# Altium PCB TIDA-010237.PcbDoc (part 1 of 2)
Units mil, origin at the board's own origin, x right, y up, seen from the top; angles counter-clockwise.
Board outline 2362.2 x 3346.46 mil, 4 copper layers (Top Layer, GND, Power, Bottom Layer), stack 61.6 mil thick; 143 components, 71 nets, 356 pads, 186 vias.
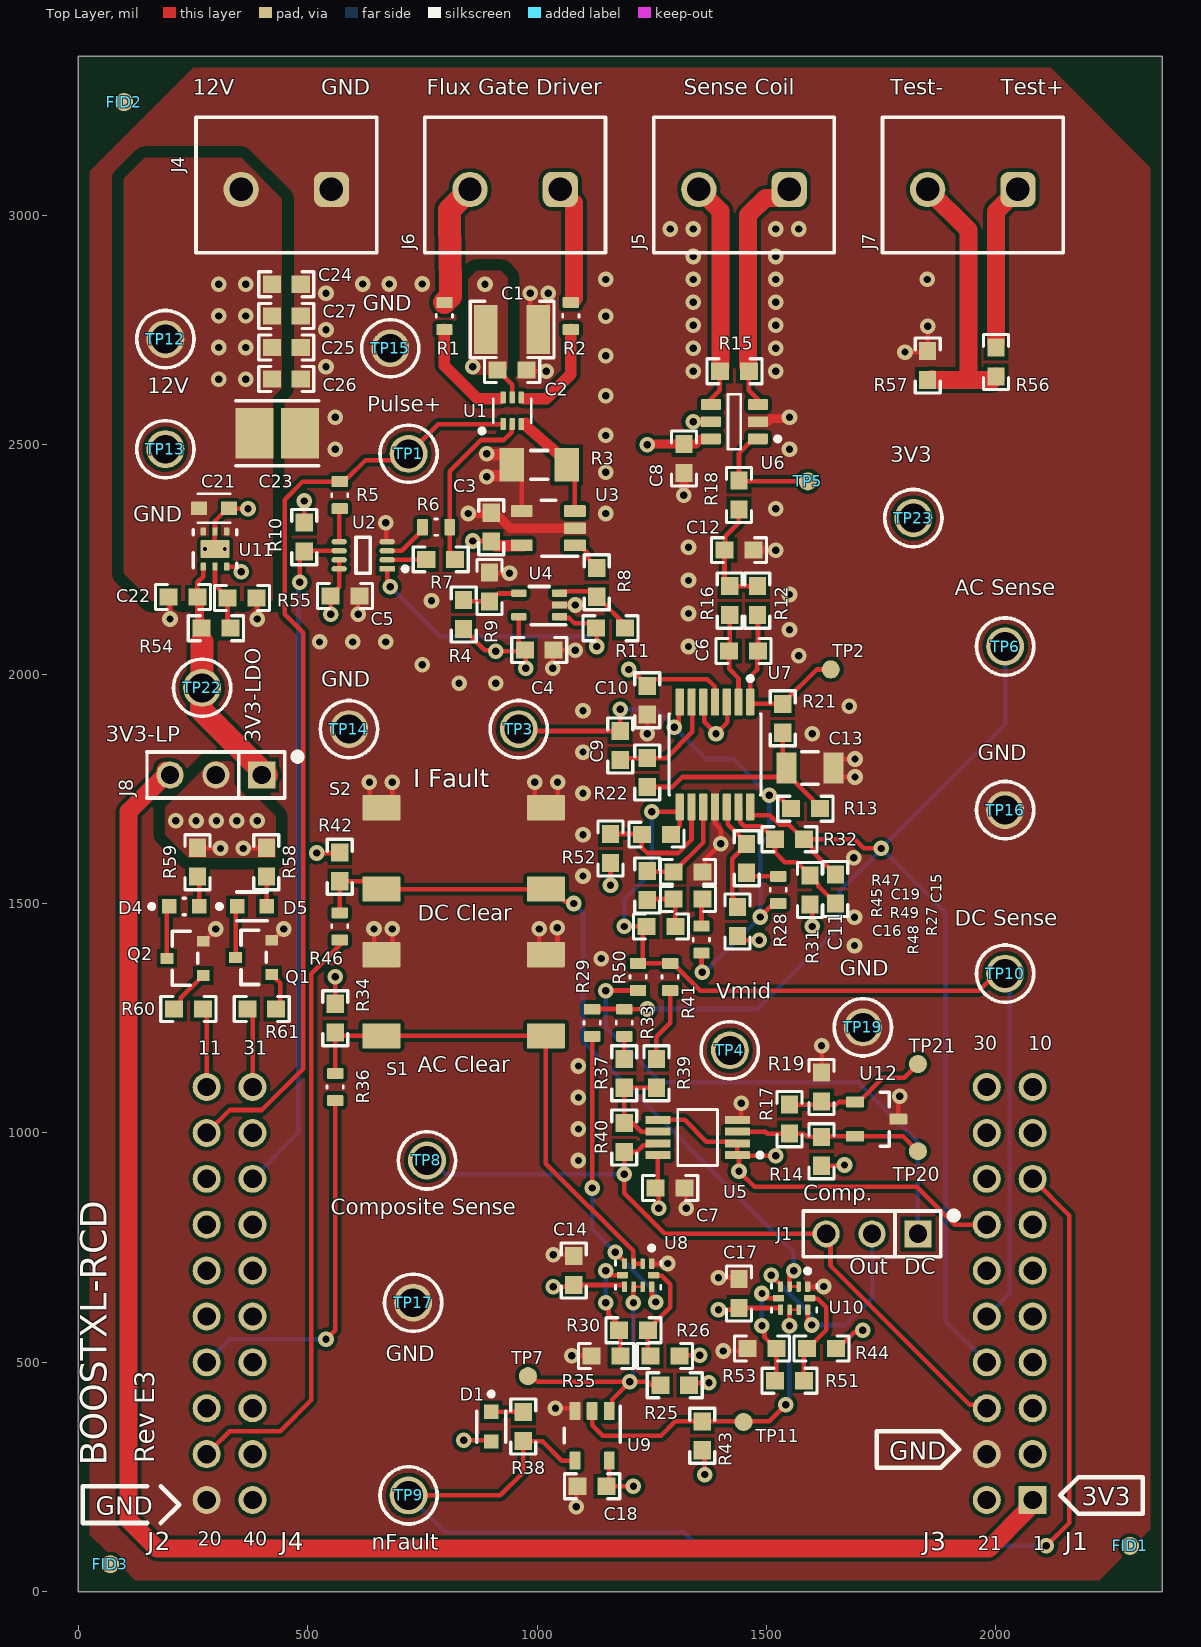
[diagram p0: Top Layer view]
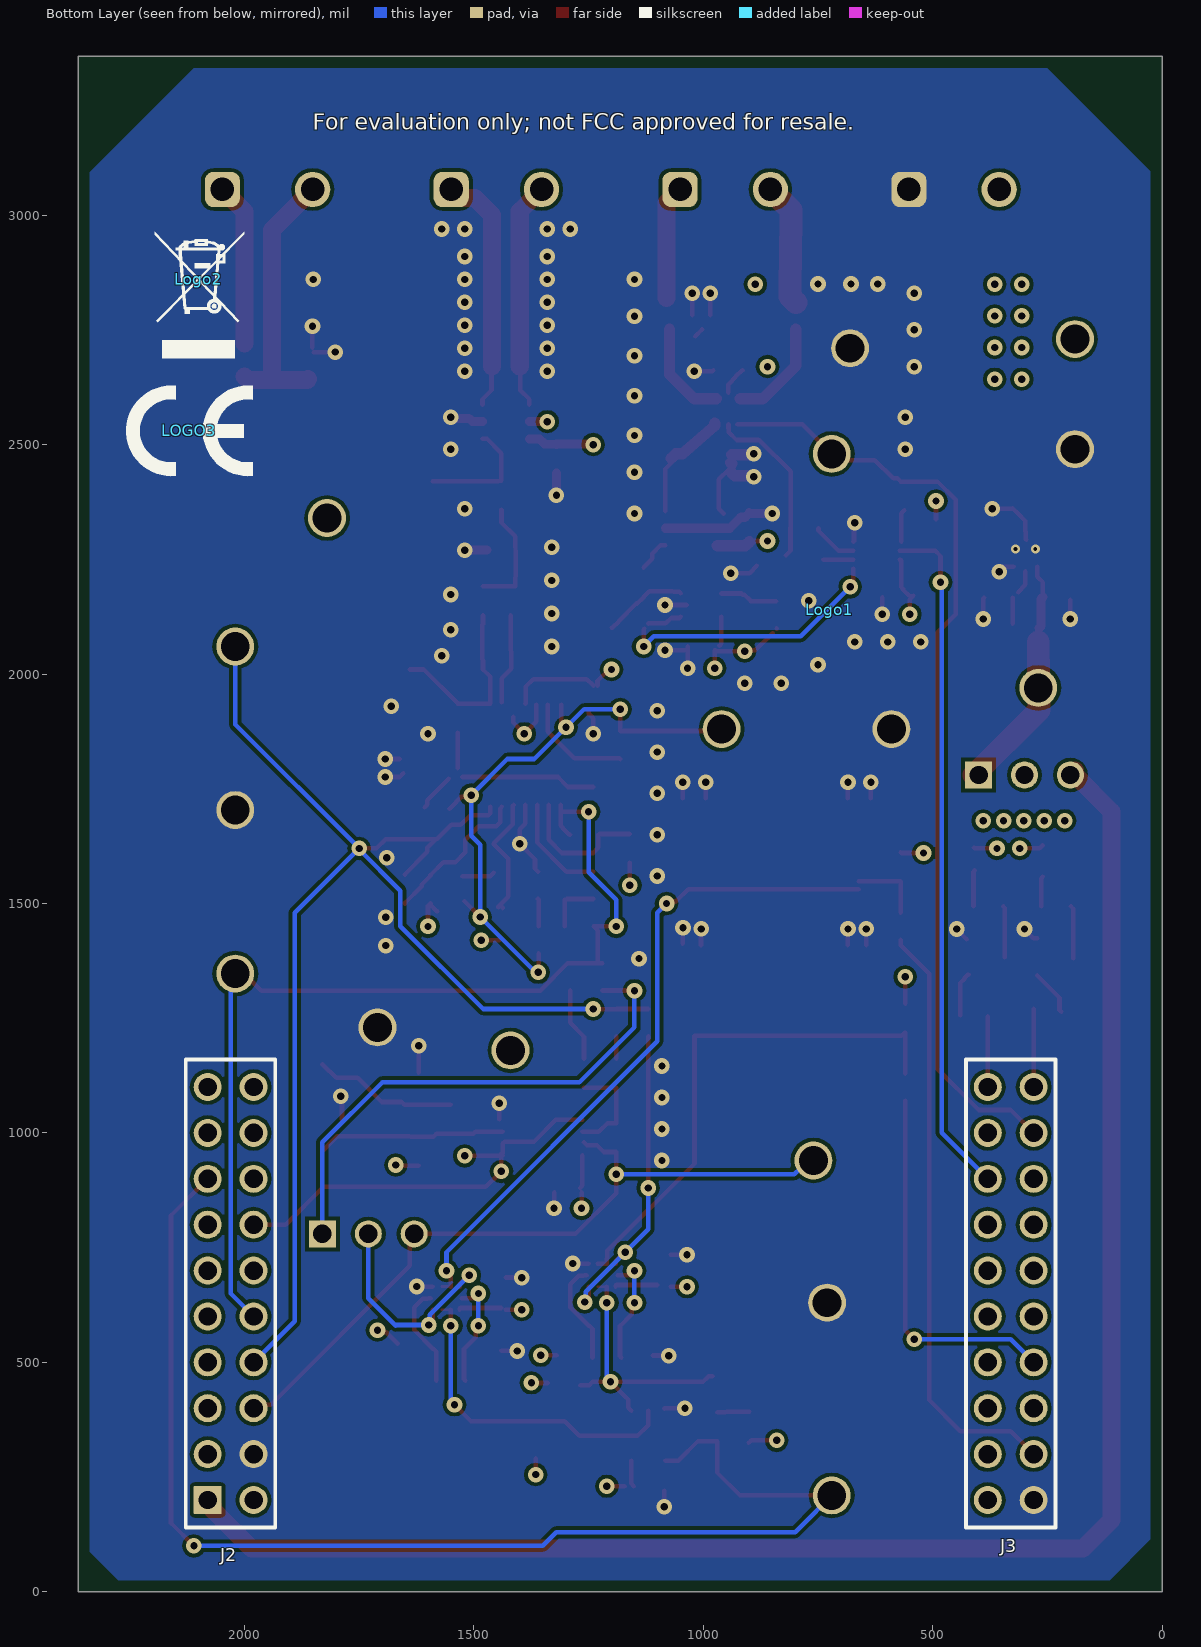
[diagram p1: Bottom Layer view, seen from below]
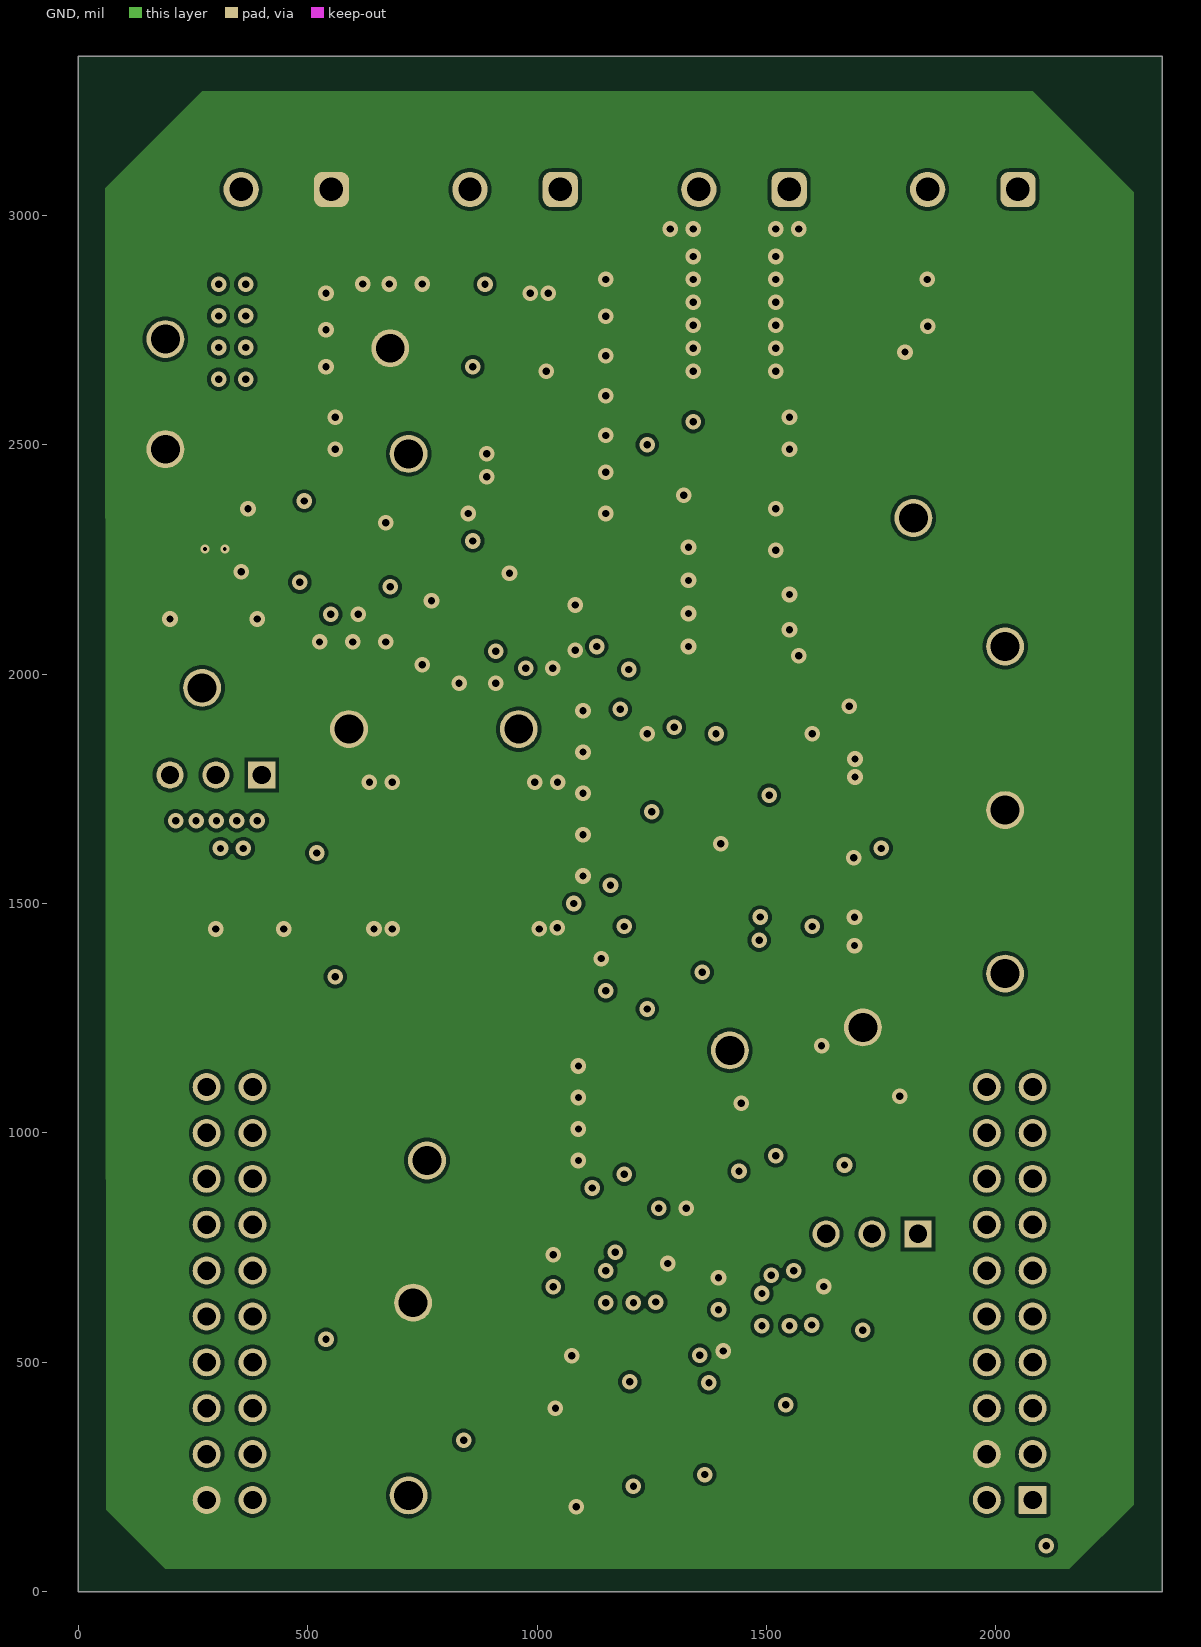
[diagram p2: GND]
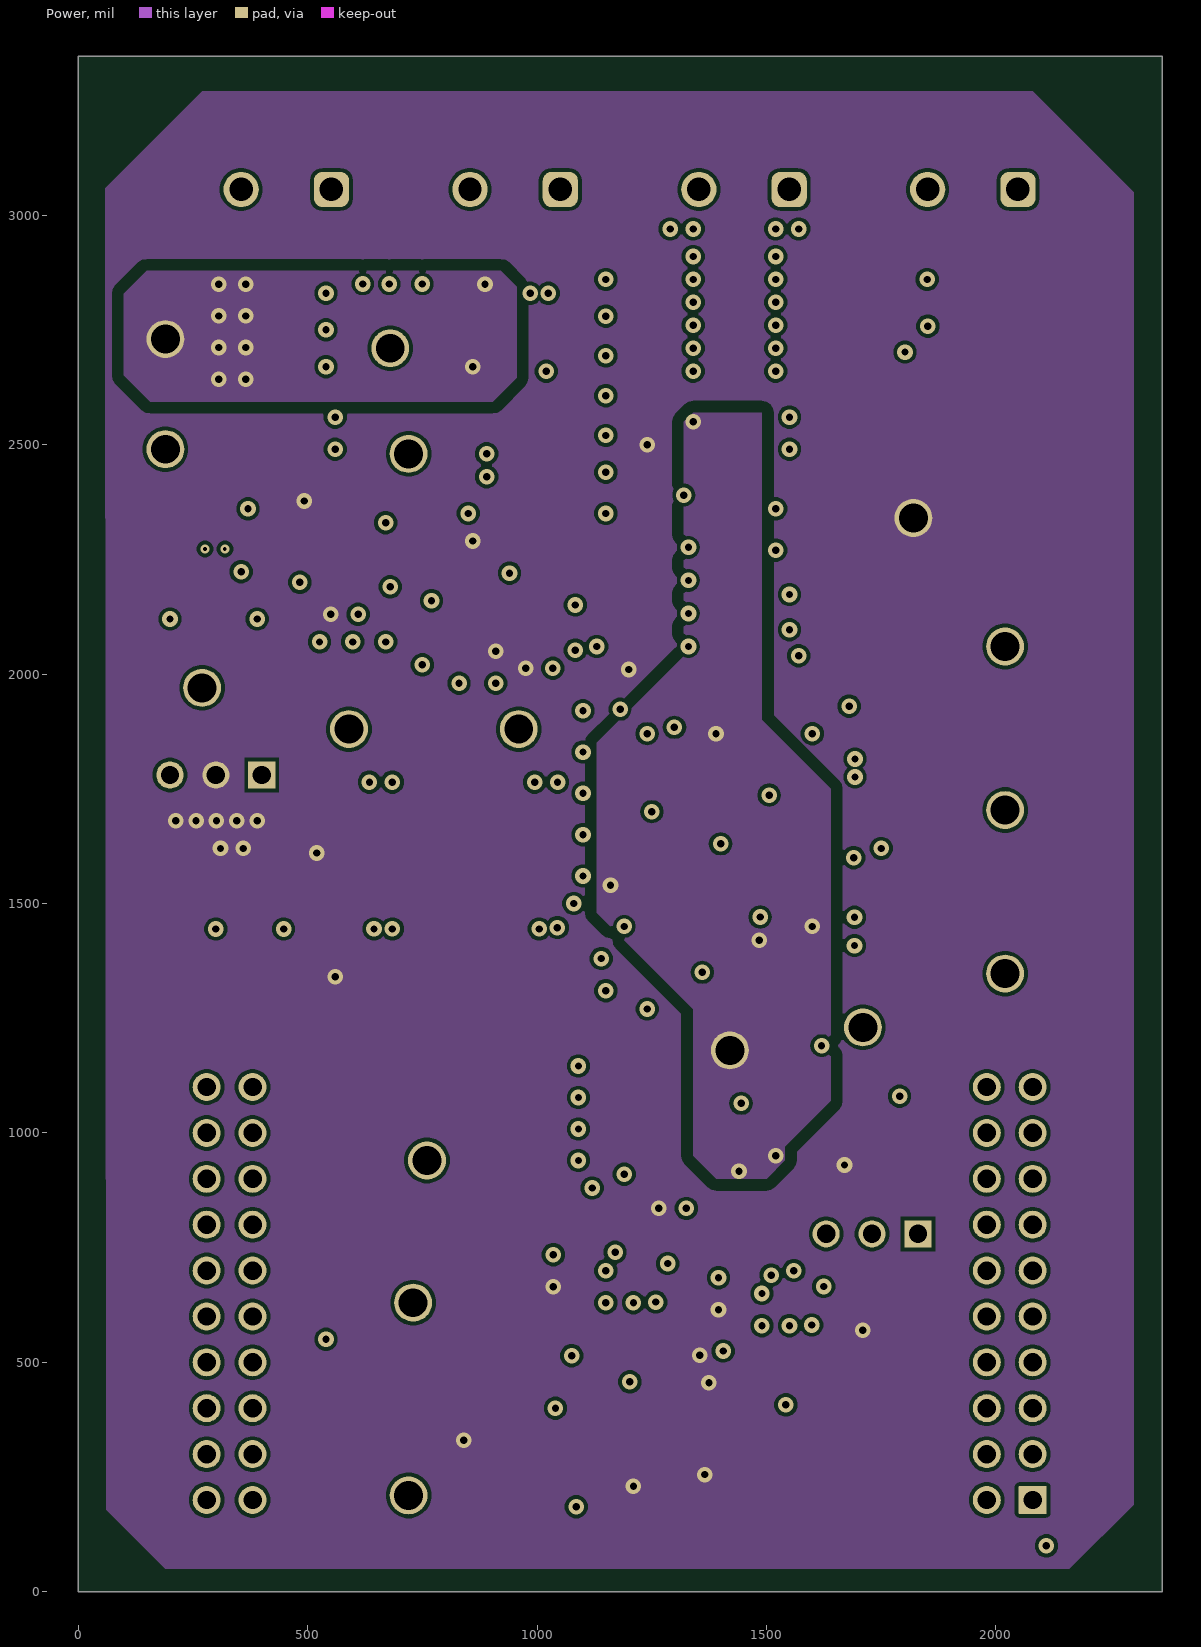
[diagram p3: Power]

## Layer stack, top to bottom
Top Solder: solder mask 0.4, Solder Resist, Dk 3.5
Top Layer: signal copper 1.4
Dielectric1: prepreg 8, FR-4, Dk 4.2
GND: signal copper 1.4
Dielectric 2: core 40, FR-4, Dk 4.2
Power: signal copper 1.4
Dielectric 3: prepreg 8, FR-4, Dk 4.2
Bottom Layer: signal copper 1.4
Bottom Solder: solder mask 0.4, Solder Resist, Dk 3.5

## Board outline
0,0 2362.2,0 2362.2,3346.46 0,3346.46

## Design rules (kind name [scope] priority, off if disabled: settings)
AcuteAngle [All] p1: minimum=4.50000000000000E+0001 checktracksonly=FALSE
AssemblyTestPointUsage [All] p1: valid=2
BoardOutlineClearance BoardOutlineClearance_MountingHoles [OnCopper and InComponentClass('Mounting Holes')] p1: gap=40 ignorepadtopadclearanceinfootprint=FALSE
BoardOutlineClearance BoardOutlineClearance_Poly [OnCopper and IsPoly] p2: gap=25 ignorepadtopadclearanceinfootprint=FALSE
BoardOutlineClearance [OnCopper and Not InComponentClass('Logo') and not InComponentClass('FiducialMark') and not InRegion(1000,500,4000,800) and not InPoly] p3: gap=75 ignorepadtopadclearanceinfootprint=FALSE
Clearance Clearance_1 [WithinRoom('TIDA-010237_Receiver_Circuit')or WithinRoom('TIDA-010237_Receiver_Circuit_1') vs WithinRoom('TIDA-010237_Receiver_Circuit')or WithinRoom('TIDA-010237_Receiver_Circuit_1')] p1: gap=7.87 ignorepadtopadclearanceinfootprint=FALSE except(0: Arc-Hole Track-Hole SMDPad-SMDPad SMDPad-THPad SMDPad-Via SMDPad-Hole THPad-Hole Via-Hole Fill-Hole Poly-Hole Region-Hole Text-Hole; 11.81: Via-Fill Via-Poly Via-Region)
Clearance Clearance_Keepouts [((IsTrack Or IsArc) And Not InPoly) And IsFree and IsKeepOut vs ((IsTrack Or IsArc) And Not InPoly) And IsFree and IsKeepOut] p2: gap=0 ignorepadtopadclearanceinfootprint=FALSE
Clearance Clearance_Poly [InPolygon] p3: gap=7.87 ignorepadtopadclearanceinfootprint=FALSE except(0: Arc-Hole Track-Hole SMDPad-Hole THPad-Hole Via-Hole Fill-Hole Poly-Hole Region-Hole Text-Hole; 25: Arc-Text Track-Text SMDPad-Via SMDPad-Text THPad-Via THPad-Text Via-Via Via-Text Fill-Fill Fill-Poly Fill-Region Fill-Text Poly-Poly Poly-Region Poly-Text Region-Region Region-Text Text-Text)
Clearance [All] p4: gap=7.87 ignorepadtopadclearanceinfootprint=FALSE except(0: Arc-Hole Track-Hole SMDPad-Hole THPad-Hole Via-Hole Fill-Hole Poly-Hole Region-Hole Text-Hole; 11.81: Via-Fill Via-Poly Via-Region)
ComponentClearance ComponentClearance_MountingHoles_FiducialMarks [InComponentClass('Mounting Holes') vs InComponentClass('FiducialMark')] p1: gap=50 collisioncheckmode=3 verticalgap=10 showdistances=FALSE
ComponentClearance ComponentClearance_Shunt [InComponentClass('Header') vs InComponentClass('Shunt')] p2: gap=0 collisioncheckmode=3 verticalgap=0 showdistances=FALSE
ComponentClearance ComponentClearance_Logo [InComponentClass('Logo')] p3: gap=50 collisioncheckmode=3 verticalgap=10 showdistances=FALSE
ComponentClearance ComponentClearance_ScrewToNut [(HasFootprint('NY PMS 440 0025 PH')) vs (HasFootprint('Keystone_1902C'))] p4: gap=5 collisioncheckmode=3 verticalgap=10 showdistances=FALSE
ComponentClearance ComponentClearance_MountingHoles [InComponentClass('Mounting Holes')] p5: gap=250 collisioncheckmode=3 verticalgap=100000 showdistances=FALSE
ComponentClearance ComponentClearance_SmallPassives [HasFootprint('0201*') or HasFootprint('0402*') or HasFootprint('0508') or HasFootprint('0603*') or HasFootprint('0612') or HasFootprint('0805*') or HasFootprint('0815*') or HasFootprint('0830*') or HasFootprint('1206*') or HasFootprint('1210*') or HasFootprint('1808*') or HasFootprint('1812*') or HasFootprint('1825*') or HasFootprint('2010*') or HasFootprint('2220*') or HasFootprint('2225*') or HasFootprint('2512*') or HasFootprint('2728*') or HasFootprint('3518*') vs HasFootprint('0201*') or HasFootprint('0402*') or HasFootprint('0508') or HasFootprint('0603*') or HasFootprint('0612') or HasFootprint('0805*') or HasFootprint('0815*') or HasFootprint('0830*') or HasFootprint('1206*') or HasFootprint('1210*') or HasFootprint('1808*') or HasFootprint('1812*') or HasFootprint('1825*') or HasFootprint('2010*') or HasFootprint('2220*') or HasFootprint('2225*') or HasFootprint('2512*') or HasFootprint('2728*') or HasFootprint('3518*')] p6: gap=14.96 collisioncheckmode=3 verticalgap=10 showdistances=FALSE
ComponentClearance ComponentClearance_THtoSMT [IsThruComponent vs IsSMTComponent] p7: gap=30 collisioncheckmode=3 verticalgap=30 showdistances=FALSE
ComponentClearance ComponentClearance_THtoTH [IsThruComponent vs IsThruComponent] p8: gap=30 collisioncheckmode=3 verticalgap=30 showdistances=FALSE
ComponentClearance [All] p9: gap=30 collisioncheckmode=3 verticalgap=10 showdistances=FALSE
DiffPairsRouting [All] p1: maxlimit=100 minlimit=10 mostfreqgap=10 toplayer_minwidth=15 toplayer_maxwidth=15 toplayer_prefwidth=15 midlayer1_minwidth=15 midlayer1_maxwidth=15 midlayer1_prefwidth=15 midlayer2_minwidth=15 midlayer2_maxwidth=15 midlayer2_prefwidth=15 bottomlayer_minwidth=15 bottomlayer_maxwidth=15 bottomlayer_prefwidth=15 maxuncoupledlength=1000
FabricationTestPointUsage TestPointUsage [All] p1: valid=2 allowmultiple=FALSE
FabricationTestpoint Testpoint [All] p1: side=3 testpointundercomponent=TRUE minsize=40 maxsize=100 preferedsize=60 minholesize=0 maxholesize=40 preferedholesize=32 testpointgrid=1 allowsidetop=TRUE allowsidebottom=TRUE usegrid=TRUE gridtolerance=0.01
FanoutControl Fanout_LCC [IsLCC] p1: bgadir=Out bgaviamode=Centered fanoutstyle=Auto fanoutdirection=Alternating viagrid=1 // Fanout_LCC (Default Rule)
FanoutControl Fanout_BGA [IsBGA] p2: bgadir=Out bgaviamode=Centered fanoutstyle=Auto fanoutdirection=Alternating viagrid=1 // Fanout_BGA (Default Rule)
FanoutControl Fanout_Default [All] p4: bgadir=Out bgaviamode=Centered fanoutstyle=Auto fanoutdirection=Alternating viagrid=1 // Fanout_Default (Default Rule)
FanoutControl Fanout_Small [(CompPinCount < 5)] p5: bgadir=Out bgaviamode=Centered fanoutstyle=Auto fanoutdirection=OutThenIn viagrid=1 // Fanout_Small (Default Rule)
HoleSize [All] p1: absolutevalues=TRUE maxlimit=251 minlimit=7.87 maxpercent=80.000 minpercent=20.000
MinimumAnnularRing MinimumAnnularRing_ThermalPadVias [IsVia and InAnyComponent] p1: minimumring=5
MinimumAnnularRing [All] p2: minimumring=8
MinimumSolderMaskSliver MinimumSolderMaskSliver_Logo [InComponentClass('Logo') vs InComponentClass('Logo')] p1: minsoldermaskwidth=0.7
MinimumSolderMaskSliver [All] p2: minsoldermaskwidth=3.94
PlaneClearance [All] p1: clearance=19.8
PlaneConnect [All] p1: planeconnectstyle=Direct reliefexpansion=10 reliefentries=4 reliefconductorwidth=10 reliefairgap=10
PolygonConnect [All] p1: connectstyle=Direct reliefconductorwidth=10 reliefentries=4 polygonreliefangle="90 Angle" airgapwidth=10
RoutingVias ThermalPadVias [IsVia and InAnyComponent] p1: holewidth=7.87 width=19.68 viastyle="Through Hole" minholewidth=7.87 minwidth=19.68 maxholewidth=12.99 maxwidth=23.62
RoutingVias [All] p2: holewidth=16 width=34 viastyle="Through Hole" minholewidth=7.87 minwidth=20 maxholewidth=40 maxwidth=65
SMDEntry [All] p1: side=TRUE corner=TRUE anyangle=FALSE
SilkToBoardRegionClearance [Not ((IsComment or IsDesignator) And (Hide <> 'False')) and not InRegion(1000,500,4000,800)] p1:
SilkToSilkClearance SilkToSilkClearance_Pb-FreeLogo [(HasFootprint('Pb-Free_Overlay_Medium') OR HasFootprint('Pb-Free_Overlay_Small')) vs (HasFootprint('Pb-Free_Overlay_Medium') OR HasFootprint('Pb-Free_Overlay_Small'))] p1: silktosilkclearance=0
SilkToSilkClearance [All] p2: silktosilkclearance=0
SilkToSolderMaskClearance SilkToComponentPadClearance [IsPad and InAnycomponent] p1: minsilkscreentomaskgap=3 clearancetoexposedcopper=TRUE
SilkToSolderMaskClearance "Silk to Solder Mask Opening" [All] p2: minsilkscreentomaskgap=1 clearancetoexposedcopper=FALSE
SolderMaskExpansion [All] p1: expansion=1.97 istentingtop=FALSE
Width [All] p1: maxlimit=50 minlimit=6 preferedwidth=10 checkconnectedcopper=TRUE
14 further rules are at their usual default settings.

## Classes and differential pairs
component class Header: J1 J8
component class TIDA-010237_ConnectorsAndPower: C21 C22 C23 C24 C25 C26 C27 D4 D5 J2 J3 J4 J5 J6 J7 J8 Q1 Q2 R54 R55 R56 R57 R58 R59 R60 R61 TP12 TP13 TP14 TP15 TP16 TP17 TP19 TP22 TP23 U11
component class TIDA-010237_Hardware: !PCB1 FID1 FID2 FID3 Logo1 Logo2 LOGO3 ZZ1 ZZ2 ZZ3 ZZ4
component class TIDA-010237_Driver_Circuit: C1 C2 C3 C4 C5 jc R1 R2 R3 R4 R5 R6 R7 R8 R9 R10 R11 TP1 U1 U2 U3 U4
component class TIDA-010237_Receiver_Circuit: C6 C7 C8 C9 C10 C11 C12 C13 C14 C15 C16 C17 C18 C19 D1 J1 R12 R13 R14 R15 R16 R17 R18 R19 R21 R22 R25 R26 R27 R28 R29 R30 R31 R32 R33 R34 R35 R36 R37 R38 R39 R40 R41 R42 R43 R44 R45 R46 R47 R48 R49 R50 R51 R52 R53 S1 S2 TP2 TP3 TP4 TP5 TP6 TP7 TP8 TP9 TP10 TP11 TP20 TP21 U5 U6 U7 U8 U9 U10 U12
component class FiducialMark: FID1 FID2 FID3
component class AssemblyNote: ZZ1 ZZ2 ZZ3 ZZ4

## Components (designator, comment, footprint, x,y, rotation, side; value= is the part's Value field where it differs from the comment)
C1 "CL32B226KAJNFNE" 1210_270 945.67,2750.94 r0 top value=22uF
C2 "06035C104KAZ2A" 0603 945.67,2662.36 r0 top value=0.1uF
C3 "EMK107B7104KA-T" 0603 900,2320 r90 top value=0.1uF
C4 "EMK107B7104KA-T" 0603 1004.72,2052.13 r0 top value=0.1uF
C5 "EMK107B7104KA-T" 0603 581.5,2170.24 r0 top value=0.1uF
C6 "EMK107B7105KAHT" 0603 1450,2050 r180 top value=1uF
C7 "EMK107B7104KA-T" 0603 1290,880 r0 top value=0.1uF
C8 "EMK107B7104KA-T" 0603 1320,2470 r270 top value=0.1uF
C9 "EMK107B7105KAHT" 0603 1181.1,1844.49 r270 top value=1uF
C10 "EMK107B7104KA-T" 0603 1240.16,1942.91 r270 top value=0.1uF
C11 "EMK107B7104KA-T" 0603 1650,1531.5 r90 top value=0.1uF
C12 "GRM1885C1H222JA01D" 0603 1440,2270 r0 top value=2200pF
C13 "1206YD226KAT2A" FP-1206-L_3_2_0_2-W_1_6_0-IPC_C 1594.49,1795.28 r0 top
C14 "EMK107B7104KA-T" 0603 1080,700 r90 top value=0.1uF
C15 "EMK107B7104KA-T" 0603 1456.69,1598.43 r270 top value=0.1uF
C16 "EMK107B7105KAHT" 0603 1270,1450 r180 top value=1uF
C17 "EMK107B7104KA-T" 0603 1440,650 r90 top value=0.1uF
C18 "EMK107B7104KA-T" 0603 1120,230 r180 top value=0.1uF
C19 "EMK107B7105KAHT" 0603 1328.74,1568.9 r0 top value=1uF
C21 "GMC10X7R105K50NT" FP-GMC10X7R105K50NT_0603-MFG 296.06,2361.18 r180 top value=1µF
C22 "EMK107BB7225MA-T" 0603 228.28,2167.98 r180 top value=2.2uF
C23 "GRM32EC81C476KE15K" FP-GRM32E-0_3-0_2-IPC_A 433.86,2524.57 r0 top
C24 "EMK107B7104KA-T" 0603 453.54,2849.37 r0 top value=0.1uF
C25 "EMK107B7104KA-T" 0603 453.54,2711.57 r0 top value=0.1uF
C26 "EMK107B7104KA-T" 0603 453.54,2642.68 r0 top value=0.1uF
C27 "EMK107B7104KA-T" 0603 453.54,2780.47 r0 top value=0.1uF
D1 "SML-D12U8WT86C" FP-SML-D12-MFG 900,360 r270 top
D4 "SML-D12P8WT86" FP-SML-D12-MFG 231.02,1493.54 r0 top
D5 "SML-D12U8WT86C" FP-SML-D12-MFG 378.66,1493.54 r0 top
FID1 "Fiducial" Fiducial10-20 2292.2,100 r0 top
FID2 "Fiducial" Fiducial10-20 100,3246.46 r0 top
FID3 "Fiducial" Fiducial10-20 70,60 r0 top
J1 "PEC03SAAN" CONN_PEC03SAAN 1730,780 r180 top
J2 "SSQ-110-03-T-D" BoosterPack_40pin_J1J3 2030,650 r0 bottom
J3 "SSQ-110-03-T-D" BoosterPack_40pin_J2J4 330,650 r0 bottom
J4 "691137710002" 691137710002 453.54,3065.91 r180 top
J5 "691137710002" 691137710002 1450.92,3065.91 r180 top
J6 "691137710002" 691137710002 952.23,3065.91 r180 top
J7 "691137710002" 691137710002 1949.61,3065.91 r180 top
J8 "PEC03SAAN" CONN_PEC03SAAN 300,1780 r180 top
Logo1 "FCC disclaimer" FCC_disclaimer 724.8,2140 r180 bottom
Logo2 "WEEE logo" WEEE_Minimum 2100,2860 r180 bottom
LOGO3 "CE Mark" CE_Mark_5mm 2120,2530 r180 bottom
Q1 "BC847C,235" FP-SOT23-MFG 382.26,1382.48 r180 top
Q2 "BC847C,235" FP-SOT23-MFG 232.76,1380.48 r180 top
R1 "560112116001" FP-560112116001_0603-MFG 798.03,2780.47 r270 top value=0
R2 "560112116001" FP-560112116001_0603-MFG 1073.62,2780.47 r270 top value=0
R3 "CRCW12063R00JNEA" FP-CRCW1206-e3-IPC_A 1004.72,2455.67 r0 top
R4 "CRCW0603536KFKEA" 0603 840,2130 r270 top value=536k
R5 "560112116001" FP-560112116001_0603-MFG 570,2390 r270 top value=0
R6 "560112116001" FP-560112116001_0603-MFG 780,2320 r180 top value=0
R7 "CRCW06031K07FKEA" 0603 790,2250 r180 top value=1.07k
R8 "CRCW060375K0JNEA" 0603 1130,2200 r270 top value=75k
R9 "RC0603FR-07143KL" 0603 896.46,2189.92 r270 top value=143k
R10 "CRCW06031K07FKEA" 0603 492.76,2298.35 r270 top value=1.07k
R11 "MCT06030C1004FP500" 0603 1160,2100 r180 top value=1.00Meg
R12 "RC0603FR-071K3L" 0603 1480,2160 r270 top value=1.30k
R13 "CRCW06031K18FKEA" 0603 1584.65,1706.69 r180 top value=1.18k
R14 "CRCW060375R0JNEA" 0603 1620,960 r90 top value=75
R15 "ERA3AEB102V" 0603 1430,2660 r0 top value=1.00k
R16 "CRCW0603750RFKEA" 0603 1420,2160 r270 top value=750
R17 "RT0603BRD076K19L" 0603 1550,1030 r270 top value=6.19k
R18 "RC0603FR-071K3L" 0603 1440,2390 r270 top value=1.30k
R19 "RT0603BRD0718K7L" 0603 1620,1100 r270 top value=18.7k
R21 "RC0603FR-07118RL" 0603 1535.43,1903.54 r270 top value=118
R22 "RC0603FR-07147RL" 0603 1240.16,1785.43 r90 top value=147
R25 "RC0603FR-0710KL" 0603 1300,450 r180 top value=10.0k
R26 "RC0603FR-0710KL" 0603 1278.5,514.09 r180 top value=10.0k
R27 "RC0603FR-0735K7L" 0603 1437.01,1460.63 r270 top value=35.7k
R28 "560112116001" FP-560112116001_0603-MFG 1525.59,1529.53 r270 top value=0
R29 "560112116001" FP-560112116001_0603-MFG 1120,1240 r90 top value=0
R30 "RC0603JR-072K7L" 0603 1210,570 r0 top value=2.7k
R31 "CRCW06032K32FKEA" 0603 1594.49,1529.53 r90 top value=2.32k
R32 "CRCW060323K2FKEA" 0603 1550,1640 r0 top value=23.2k
R33 "560112116001" FP-560112116001_0603-MFG 1190,1240 r90 top value=0
R34 "RC0603FR-0710KL" 0603 560,1250 r270 top value=10.0k
R35 "RC0603FR-0710KL" 0603 1150.55,514.09 r180 top value=10.0k
R36 "560112116001" FP-560112116001_0603-MFG 560,1100 r90 top value=0
R37 "RC0603FR-071K3L" 0603 1190,1130 r270 top value=1.30k
R38 "RC0603FR-07147RL" 0603 970,360 r90 top value=147
R39 "RT0603DRE0713KL" 0603 1260,1130 r270 top value=13.0k
R40 "RT0603DRE0718K2L" 0603 1190,990 r270 top value=18.2k
R41 "560112116001" FP-560112116001_0603-MFG 1290,1340 r270 top value=0
R42 "RC0603FR-0710KL" 0603 570,1580 r270 top value=10.0k
R43 "RC0603FR-0710KL" 0603 1360,340 r90 top value=10.0k
R44 "RC0603FR-0710KL" 0603 1620,530 r180 top value=10.0k
R45 "CRCW060323K2FKEA" 0603 1240.16,1539.37 r90 top value=23.2k
R46 "560112116001" FP-560112116001_0603-MFG 570,1450 r90 top value=0
R47 "CRCW06032K49FKEA" 0603 1260,1650 r0 top value=2.49k
R48 "560112116001" FP-560112116001_0603-MFG 1358.27,1421.26 r270 top value=0
R49 "CRCW060310K5FKEA" 0603 1328.74,1509.84 r180 top value=10.5k
R50 "560112116001" FP-560112116001_0603-MFG 1220,1340 r90 top value=0
R51 "RT0603DRE0712K1L" 0603 1550,460 r0 top value=12.1k
R52 "CRCW06032K49FKEA" 0603 1160,1620 r90 top value=2.49k
R53 "RC0603FR-0710KL" 0603 1490,530 r180 top value=10.0k
R54 "RC0603FR-0775KL" 0603 300,2100 r180 top value=75.0k
R55 "RC0603FR-0724KL" 0603 356.8,2166.03 r180 top value=24.0k
R56 "RC0603JR-07270RL" 0603 2000,2680 r90 top value=270
R57 "RC0603JR-07270RL" 0603 1851.18,2672.2 r270 top value=270
R58 "RC0603FR-07118RL" 0603 410,1590 r90 top value=118
R59 "RC0603FR-07118RL" 0603 260,1590 r90 top value=118
R60 "RC0603FR-071K3L" 0603 240,1270 r0 top value=1.30k
R61 "RC0603FR-071K3L" 0603 400,1270 r0 top value=1.30k
S1 "FSM4JSMA" SW_FSM4JSMA 840,1300 r270 top
S2 "FSM4JSMA" SW_FSM4JSMA 840,1620 r270 top
TP1 "5012" KSTN-5012_V 720,2480 r0 top
TP2 "TP_SM_1MM" TP_SM_1MM 1640,2010 r90 top
TP3 "5012" KSTN-5012_V 960,1880 r0 top
TP4 "5010" KSTN-5010_V 1420,1180 r270 top
TP5 "TP_SM_1MM" TP_SM_1MM 1590,2420 r90 top
TP6 "5012" KSTN-5012_V 2020,2060 r180 top
TP7 "TP_SM_1MM" TP_SM_1MM 980,470 r0 top
TP8 "5012" KSTN-5012_V 760,940 r0 top
TP9 "5012" KSTN-5012_V 720,210 r0 top
TP10 "5012" KSTN-5012_V 2020,1347.17 r180 top
TP11 "TP_SM_1MM" TP_SM_1MM 1450,370 r90 top
TP12 "5010" KSTN-5010_V 190,2730 r0 top
TP13 "5011" KSTN-5011_V 190,2490 r0 top
TP14 "5011" KSTN-5011_V 590,1880 r270 top
TP15 "5011" KSTN-5011_V 680,2710 r0 top
TP16 "5011" KSTN-5011_V 2020,1703.58 r180 top
TP17 "5011" KSTN-5011_V 730,630 r0 top
TP19 "5011" KSTN-5011_V 1710,1230 r0 top
TP20 "TP_SM_1MM" TP_SM_1MM 1830,960 r90 top
TP21 "TP_SM_1MM" TP_SM_1MM 1830,1150 r90 top
TP22 "5010" KSTN-5010_V 270,1970 r0 top
TP23 "5010" KSTN-5010_V 1820,2340 r0 top
U1 "DRV8220DRLR" DRL0006A-MFG 945.67,2573.78 r90 top
U2 "SN74LVC2G74DCUR" FP-DCU0008A-IPC_C 620.87,2258.82 r180 top
U3 "INA293A1IDBVR" DBV0005A_M 1024.41,2317.87 r180 top
U4 "TLV7011DCKR" DCK0005A_N 1004.72,2150.55 r180 top
U5 "OPA2323IDGKR" DGK0008A-MFG 1350,990 r180 top
U6 "INA600AIDBVR" DBV0006A-MFG 1430,2550 r180 top
U7 "OPA4383PWR" PW0014A-MFG 1387.8,1824.8 r270 top
U8 "TLV9022LRUG" RUG0010A-MFG 1220,690 r180 top
U9 "SN74AHCT1G08DBVT" DBV0005A_N 1120,340 r270 top
U10 "TLV9022LRUG" RUG0010A-MFG 1560,640 r180 top
U11 "TLV76701DRVR" DRV0006A 298.03,2272.6 r90 top
U12 "TLV431BQDBZR" DBZ0003A_N 1740,1030 r0 top
ZZ1 "These assemblies are ESD sensitive, ESD precautions shall be observed." AssemblyNote 0,3646.46 r0 top
ZZ2 "These assemblies must be clean and free from flux and all contaminants. Use of no clean flux is not acceptable." AssemblyNote 0,3546.46 r0 top
ZZ3 "These assemblies must comply with workmanship standards IPC-A-610 Class 2, unless otherwise specified." AssemblyNote 0,3446.46 r0 top
ZZ4 "This Assembly Note is for PCB labels only" AssemblyNoteLabel 0,3746.46 r0 top

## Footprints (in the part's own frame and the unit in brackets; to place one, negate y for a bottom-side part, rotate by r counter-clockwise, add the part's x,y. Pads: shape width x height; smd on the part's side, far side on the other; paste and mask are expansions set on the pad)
0603 [mm] "0603 from SM-752 data"
  rect 1x0.95 smd: 1(-0.8,0) 2(0.8,0)
  silkscreen extent -1.52,-0.69 1.52,0.69, body extent -0.87,-0.47 0.87,0.47, height 1
1210_270 [mm] "1210"
  rect 1.3x2.7 smd: 1(-1.45,0) 2(1.45,0)
  silkscreen extent -2.32,-1.57 2.32,1.57, body extent -1.7,-1.35 1.7,1.35, height 2.7
691137710002 [mm] "Horizontal Cable Entry with Pressure Clamp, pitch 5mm, 02p"
  rrect50% 1.95x1.95 hole 1.3: 1(-2.5,0.25)
  round 1.95 hole 1.3: 2(2.5,0.25)
  silkscreen extent -5,-3.75 5,3.75, body extent -5,-3.75 5,3.75, height 11.6
AssemblyNote [mil] "Assembly Note"
AssemblyNoteLabel [mil] "Assembly Note for PCB Labels"
BoosterPack_40pin_J1J3 [mm] "Receptacle, 2.54mm, 10x2, TH"
  rrect6% 1.55x1.55 hole 1.02: 1(1.27,11.43)
  round 1.55 hole 1.02: 2(1.27,8.89) 3(1.27,6.35) 4(1.27,3.81) 5(1.27,1.27) 6(1.27,-1.27) 7(1.27,-3.81) 8(1.27,-6.35) 9(1.27,-8.89) 10(1.27,-11.43) 21(-1.27,11.43) 22(-1.27,8.89) 23(-1.27,6.35) 24(-1.27,3.81) 25(-1.27,1.27) 26(-1.27,-1.27) 27(-1.27,-3.81) 28(-1.27,-6.35) 29(-1.27,-8.89) 30(-1.27,-11.43)
  silkscreen extent -2.48,-12.95 2.48,12.95, body extent -2.48,-12.95 2.48,12.95, height 8.51
BoosterPack_40pin_J2J4 [mm] "Receptacle, 2.54mm, 10x2, TH"
  round 1.55 hole 1.02: 11(-1.27,-11.43) 12(-1.27,-8.89) 13(-1.27,-6.35) 14(-1.27,-3.81) 15(-1.27,-1.27) 16(-1.27,1.27) 17(-1.27,3.81) 18(-1.27,6.35) 19(-1.27,8.89) 20(-1.27,11.43) 31(1.27,-11.43) 32(1.27,-8.89) 33(1.27,-6.35) 34(1.27,-3.81) 35(1.27,-1.27) 36(1.27,1.27) 37(1.27,3.81) 38(1.27,6.35) 39(1.27,8.89) 40(1.27,11.43)
  silkscreen extent -2.48,-12.95 2.48,12.95, body extent -2.48,-12.95 2.48,12.95, height 8.51
CE_Mark_5mm [mil] "Minimum text height for CE Mark"
  silkscreen extent -138,-98 138,98
CONN_PEC03SAAN [mm] "SULLINS"
  rect 1.5x1.5 hole 1.016: 1(-2.54,0)
  round 1.5 hole 1.016: 2(0,0) 3(2.54,0)
  silkscreen extent -4.72,-1.27 3.81,1.27, body extent -3.84,-1.3 3.84,1.3, height 8.38
DBV0005A_M [mm] "SOT23, 5-Leads, Body 2.9x1.6mm, Pitch 0.95mm, Lead Span 2.8mm, IPC Low Density"
  rrect15% 1.2x0.65 smd: 1(-1.475,0.95) 2(-1.475,0) 3(-1.475,-0.95) 4(1.475,-0.95) 5(1.475,0.95)
  silkscreen extent -1.63,-1.55 0.38,1.55, body extent -1.42,-1.46 1.42,1.46, height 1.09
DBV0005A_N [mm] "SOT23, 5-Leads, Body 2.9x1.6mm, Pitch 0.95mm, Lead Span 2.8mm, IPC Medium Density"
  rrect17% 1x0.6 smd: 1(-1.375,0.95) 2(-1.375,0) 3(-1.375,-0.95) 4(1.375,-0.95) 5(1.375,0.95)
  silkscreen extent -1.63,-1.55 0.38,1.55, body extent -1.42,-1.46 1.42,1.46, height 1.09
DBV0006A-MFG [mm] "Recommended Land Pattern"
  rrect17% 1.1x0.6 smd paste+0 mask+0: 1(-1.3,0.95) 2(-1.3,0) 3(-1.3,-0.95) 4(1.3,-0.95) 5(1.3,0) 6(1.3,0.95)
  silkscreen extent -2.53,-1.53 0.35,1.53, body extent -1.4,-1.45 1.4,1.45, height 1.45
DBZ0003A_N [mm] "SOT23, 3-Leads, Body 2.9x1.3mm, Pitch 0.95mm, Lead Span 2.4mm, IPC Medium Density"
  rrect17% 1x0.6 smd: 1(-1.2,0.95) 2(-1.2,-0.95) 3(1.2,0)
  silkscreen extent 0.2,-1.5 0.7,1.5, body extent -1.26,-1.46 1.26,1.46, height 0.98
DCK0005A_N [mm] "SOT353, 5-Leads, Body 2x1.3mm, Pitch 0.65mm, Lead Span 2.1mm, IPC Medium Density"
  rrect25% 0.85x0.4 smd: 1(-1.125,0.65) 2(-1.125,0) 3(-1.125,-0.65) 4(1.125,-0.65) 5(1.125,0.65)
  silkscreen extent -1.48,-1.02 0.55,1.1, body extent -1.14,-1 1.14,1, height 0.95
DGK0008A-MFG [mm] "Recommended Land Pattern"
  rrect22% 1.4x0.45 smd paste+0 mask+0: 1(-2.2,0.975) 2(-2.2,0.325) 3(-2.2,-0.325) 4(-2.2,-0.975) 5(2.2,-0.975) 6(2.2,-0.325) 7(2.2,0.325) 8(2.2,0.975)
  silkscreen extent -3.58,-1.55 1.1,1.55, body extent -2.45,-1.5 2.45,1.5, height 1.1
DRL0006A-MFG [mm]
  rrect33% 0.67x0.3 smd paste+0 mask+0: 1(-0.74,0.5) 2(-0.74,0) 3(-0.74,-0.5) 4(0.74,-0.5) 5(0.74,0) 6(0.74,0.5)
  silkscreen extent -1.24,-1.05 0.65,1.79, body extent -1.17,-1.1 1.17,1.1, height 0.25
DRV0006A [mm] "SON, 6-Leads, Body 2x2mm, Pitch 0.65mm, Thermal Pad 1.6x1mm, TI Recommended"
  rrect33% 0.45x0.3 smd: 1(-0.975,0.65) 2(-0.975,0) 3(-0.975,-0.65) 4(0.975,-0.65) 5(0.975,0) 6(0.975,0.65)
  rrect14% 1x0.7 on Top Paste: 7(0,0.45) 7(0,-0.45)
  rrect10% 1x1.6 smd paste-0.5: 7(0,0)
  silkscreen extent -1.05,-1.2 1.05,1.2, body extent -1.05,-1.05 1.05,1.05, height 0.81
FCC_disclaimer [mil]
Fiducial10-20 [mm]
  round 1 smd mask+0.5: 1(0,0)
FP-1206-L_3_2_0_2-W_1_6_0-IPC_C [mil]
  rect 43.49x67.17 smd paste+0 mask+0: 1(-51.21,0) 2(51.21,0)
  silkscreen extent -18,-35 18,35, body extent -63,-31 63,31, height 90
FP-560112116001_0603-MFG [mm] "Recommended Land Pattern"
  rrect17% 0.6x0.9 smd paste+0 mask+0: 1(-0.75,0) 2(0.75,0)
  silkscreen extent -0.08,-0.45 0.08,0.45, body extent -0.8,-0.4 0.8,0.4, height 0.6
FP-CRCW1206-e3-IPC_A [mil]
  rect 53.39x73.16 smd paste+0 mask+0: 1(-60.08,0) 2(60.08,0)
  silkscreen extent -19,-31 19,31, body extent -63,-31 63,31, height 24
FP-DCU0008A-IPC_C [mm]
  rect 0.86x0.297 smd paste+0 mask+0: 1(-1.326,0.75)
  rrect100% 0.86x0.297 smd paste+0 mask+0: 2(-1.326,0.25) 3(-1.326,-0.25) 4(-1.326,-0.75) 5(1.326,-0.75) 6(1.326,-0.25) 7(1.326,0.25) 8(1.326,0.75)
  silkscreen extent -2.46,-1 0.4,1, body extent -1.86,-1.1 1.86,1.1, height 0.25
FP-GMC10X7R105K50NT_0603-MFG [mil]
  rrect13% 35x30 smd paste+0 mask+0: 1(-32.5,0) 2(32.5,0)
  silkscreen extent -35,-31 35,31, body extent -54,-24 54,24, height 10
FP-GRM32E-0_3-0_2-IPC_A [mil]
  rect 82.79x110.48 smd paste+0 mask+0: 1(-49.24,0) 2(49.24,0)
  silkscreen extent -91,-71 91,71, body extent -110,-75 110,75, height 10
FP-SML-D12-MFG [mm]
  rect 0.8x0.8 smd paste+0 mask+0: 1(-0.825,0) 2(0.825,0)
  silkscreen extent -1.92,-0.8 0.85,0.8, body extent -1.33,-0.55 1.33,0.55, height 0.25
FP-SOT23-MFG [mm]
  rect 0.7x0.6 smd paste-1000 mask+0: 1(-1,0.95) 2(-1,-0.95) 3(1,0)
  silkscreen extent -0.7,-1.5 0.7,1.5, body extent -1.5,-1.65 1.5,1.65, height 0.25
KSTN-5010_V [mm] "Test Point, Dia 3.17mm"
  round 2.1 hole 1.6: 1(0,0)
  silkscreen extent -1.58,-1.59 1.58,1.59, body extent -1.59,-1.59 1.59,1.59, height 8.13
KSTN-5011_V [mm] "Test Point, Dia 3.17mm"
  round 2.1 hole 1.6: 1(0,0)
  silkscreen extent -1.59,-1.58 1.59,1.58, body extent -1.59,-1.59 1.59,1.59, height 8.13
KSTN-5012_V [mm] "Test Point, Dia 3.17mm"
  round 2.1 hole 1.6: 1(0,0)
  silkscreen extent -1.59,-1.58 1.59,1.58, body extent -1.59,-1.59 1.59,1.59, height 8.13
PW0014A-MFG [mm] "Recommended Land Pattern"
  rrect22% 1.5x0.45 smd paste+0 mask+0: 1(-2.9,1.95) 2(-2.9,1.3) 3(-2.9,0.65) 4(-2.9,0) 5(-2.9,-0.65) 6(-2.9,-1.3) 7(-2.9,-1.95) 8(2.9,-1.95) 9(2.9,-1.3) 10(2.9,-0.65) 11(2.9,0) 12(2.9,0.65) 13(2.9,1.3) 14(2.9,1.95)
  silkscreen extent -4.32,-2.55 2.25,2.55, body extent -3.2,-2.5 3.2,2.5, height 1.2
RUG0010A-MFG [mm]
  rrect33% 0.3x0.575 smd paste-1000 mask+0: 1(-0.75,-0.637) 4(0.75,-0.637) 6(0.75,0.637) 9(-0.75,0.637)
  rrect40% 0.25x0.575 smd paste-1000 mask+0: 2(-0.25,-0.637) 3(0.25,-0.637) 7(0.25,0.637) 8(-0.25,0.637)
  rrect29% 0.63x0.35 smd paste-1000 mask+0: 5(0.86,0) 10(-0.86,0)
  silkscreen extent -1.25,-1.62 1.25,0.77, body extent -1.28,-1.02 1.28,1.02, height 0.25
SW_FSM4JSMA [mm] "Alcoswitch"
  rrect7% 1.4x2.1 smd: 1(2.25,4.55) 2(2.25,-4.55) 3(-2.25,4.55) 4(-2.25,-4.55)
  body extent -3,-5 3,5, height 5.09
TP_SM_1MM [mm] "1mm Test Point, SMT"
  round 1 smd paste-0.5: 1(0,0)
WEEE_Minimum [mil] "WEEElie bin"
  silkscreen extent -95,-172 99,104

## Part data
C1: library part CMP-0080066-1, "CAP, CERM, 22 µF, 25 V,+/- 10%, X7R, 1210", Cap_Case=1210, Manufacturer="Samsung Electro-Mechanics", Supplier Part Number 1=1276-3391-1-ND, TempCo=X7R, Tolerance_%=10%, Value2=25V, ValueDisplayed=22µF
C2: library part CMP-0079095-1, "CAP, CERM, 0.1 µF, 50 V,+/- 10%, X7R, AEC-Q200 Grade 1, 0603", Cap_Case=0603, Manufacturer=AVX, Supplier Part Number 1=478-3540-1-ND, TempCo=X7R, Tolerance_%=10%, Value2=50V, ValueDisplayed=0.1µF
C3 C4 C5 C7 C8 C10 C11 C14 C15 C17 C18 C24 C25 C26 C27: library part CMP-0007119-4, "CAP, CERM, 0.1 uF, 16 V, +/- 10%, X7R, 0603", Cap_Case=0603, Manufacturer="Taiyo Yuden", Supplier Part Number 1=587-1240-1-ND, TempCo=X7R, Tolerance_%=10%, Value1=Unknown, Value2=16V, ValueDisplayed=0.1uF
C6 C9 C16 C19: library part CMP-0080104-1, "CAP, CERM, 1 µF, 16 V,+/- 10%, X7R, AEC-Q200 Grade 1, 0603", Cap_Case=0603, Manufacturer="Taiyo Yuden", Supplier Part Number 1=587-3305-1-ND, TempCo=X7R, Tolerance_%=10%, Value2=16V, ValueDisplayed=1µF
C12: library part CMP-0007198-2, "CAP, CERM, 2200 pF, 50 V, +/- 5%, C0G/NP0, 0603", Cap_Case=0603, Manufacturer=MuRata, Supplier Part Number 1=490-1459-1-ND, TempCo=C0G/NP0, Tolerance_%=5%, Value1=Unknown, Value2=50V, ValueDisplayed=2200pF
C13: library part CMP-1037-04992-2, "General Purpose Ceramic Capacitor, 1206, 22uF, 10%, X5R, 15%, 16V", Capacitance=22uF, Case Code (Imperial)=1206, Case Code (Metric)=3216, Dielectric=X5R, Max Operating Temperature=85°C, Min Operating Temperature=-55°C, Package Quantity=1, Tolerance=10%, Voltage Rating=16V
C21: library part CMP-0095295-1, "1 µF ±10% 50V Ceramic Capacitor X7R 0603 (1608 Metric)", Digikey Part Number=2571-GMC10X7R105K50NTTR-ND, Manufacturer="Cal-Chip Electronics", Operating Temperature Range="-55°C to +125°C", TempCo=30ppm/°C, Temperature Characteristic=X7R, Tolerance_%=10%, ValueDisplayed=1uF
C22: library part CMP-0064934-3, "CAP, CERM, 2.2 uF, 16 V,+/- 10%, X7R, 0603", Cap_Case=0603, Manufacturer="Taiyo Yuden", Supplier Part Number 1=587-4864-1-ND, TempCo=X7R, Tolerance_%=10%, Value1=Unknown, Value2=16V, ValueDisplayed=2.2uF
C23: library part CMP-06035-017875-1, "Chip Multilayer Ceramic Capacitors for General Purpose, 1210, 47uF, X6S, 22%, 10%, 16V", Capacitance=47uF, Case/Package=1210, Dielectric=X6S, Tolerance=10%, Voltage Rating (DC)=16V
D1 D5: library part CMP-08952-000014-1, "LED RED 1608 SMD", Colour=Red, Forward Current=20mA, Forward Voltage=2.2V, Manufacturer=Rohm, Package=SML-D12, Power Dissipation=54mW, Reverse Voltage=5V, Temperature="-40°C to +85°C", Temperature Range High=+85°C, Temperature Range Low=-40°C
D4: library part CMP-08952-000019-1, "LED GREEN DIFFUSED 0603 SMD", Colour=Green, Forward Current=20mA, Forward Voltage=2.2V, Manufacturer=Rohm, Package=SML-D12, Power Dissipation=54mW, Reverse Voltage=5V, Temperature="-40°C to +85°C", Temperature Range High=+85°C, Temperature Range Low=-40°C
FID1 FID2 FID3: library part CMP-0077181-1, "Fiducial mark.  There is nothing to buy or mount.", Manufacturer=N/A
J1 J8: library part CMP-0002338-1, "Header, 100mil, 3x1, Tin, TH", Color=Black, Current_A=3A, Manufacturer="Sullins Connector Solutions", Supplier Part Number 1=S1012E-03-ND, Voltage_V=1.8kV
J2: library part CMP-0003837-4, "Receptacle, 2.54mm, 10x2, Tin, TH", Alternate Manufacturer="Major League Electronics", Alternate PartNumber=CRD-081413-A-G, Manufacturer=Samtec, Supplier Part Number 1=SAM1204-10-ND
J3: library part CMP-0078266-4, "Receptacle, 2.54mm, 10x2, Tin, TH", Alternate Manufacturer="Major League Electronics", Alternate PartNumber=CRD-081413-A-G, Manufacturer=Samtec, Supplier Part Number 1=SAM1204-10-ND
J4 J5 J6 J7: library part CMP-1502-03324-2, Current Rating=16A, Max Operating Temperature=120°C, Min Operating Temperature=-30°C, Voltage Rating=300V
Logo1: library part CMP-0074847-1, "FCC_disclaimer"
Logo2: library part CMP-0074769-4, Manufacturer="Texas Instruments"
LOGO3: library part CMP-0074844-2, Manufacturer="Texas Instruments"
Q1 Q2: library part CMP-14406-000033-1, "TRANS NPN 45V 100MA TO236AB"
R1 R2 R5 R6 R28 R29 R33 R36 R41 R46 R48 R50: library part CMP-0125813-1, "0 Ohms Jumper Chip Resistor 0603 (1608 Metric) Anti-Sulfur Thick Film", Digikey Part Number=732-560112116001CT-ND, Manufacturer="Wurth Electronics", Max Current=1A, Mouser Part Number=710-560112116001, Operating Temperature Range="-55°C to +155°C", Power_W=100mW
R3: library part CMP-1014-00013-3, "RES Thick Film, 3Ω, 5%, 0.25W, 200ppm/°C, 1206", Case Code (Imperial)=1206, Case Code (Metric)=3216, Max Operating Temperature=155°C, Max Power Dissipation=250mW, Min Operating Temperature=-55°C, Package Quantity=1, Resistance=3R, Temperature Coefficient=200ppm/°C, Tolerance=5%, Voltage Rating=200V
R4: library part CMP-0022488-1, "RES, 536 k, 1%, 0.1 W, 0603", Manufacturer=Vishay-Dale, Power_W=100mW, Supplier Part Number 1=541-536KHCT-ND, TempCo="100 ppm/C", Tolerance_%=1%, Value2=0.1W, Value_Code=536k
R7 R10: library part CMP-0022112-4, "RES, 1.07 k, 1%, 0.1 W, AEC-Q200 Grade 0, 0603", Manufacturer=Vishay-Dale, Power_W=100mW, Supplier Part Number 1=541-1.07KHCT-ND, TempCo="100 ppm/C", Tolerance_%=1%, Value2=0.1W, Value_Code=1k07, ValueDisplayed=1.07k
R8: library part CMP-0025853-1, "RES, 75 k, 5%, 0.1 W, 0603", Manufacturer=Vishay-Dale, Power_W=100mW, Supplier Part Number 1=541-75KGCT-ND, TempCo="200 ppm/C", Tolerance_%=5%, Value2=0.1W, Value_Code=75k0, ValueDisplayed=75k
R9: library part CMP-0022798-4, "RES, 143 k, 1%, 0.1 W, 0603", Manufacturer=Yageo, Power_W=100mW, Supplier Part Number 1=311-143KHRCT-ND, TempCo="100 ppm/C", Tolerance_%=1%, Value2=0.1W, Value_Code=143k
R11: library part CMP-0022731-2, "RES, 1.00 M, 1%, 0.125 W, 0603", Manufacturer=Vishay/Beyschlag, Power_W=125mW, Supplier Part Number 1=MCT0603-1.00M-CFCT-ND, TempCo="50 ppm/C", Tolerance_%=1%, Value2=0.125W, Value_Code=1M00, ValueDisplayed=1.00M
R12 R18 R37 R60 R61: library part CMP-0022877-5, "RES, 1.30 k, 1%, 0.1 W, 0603", Manufacturer=Yageo, Power_W=100mW, Supplier Part Number 1=311-1.30KHRCT-ND, TempCo="100 ppm/C", Tolerance_%=1%, Value2=0.1W, Value_Code=1k30, ValueDisplayed=1.30k
R13: library part CMP-0022116-4, "RES, 1.18 k, 1%, 0.1 W, AEC-Q200 Grade 0, 0603", Manufacturer=Vishay-Dale, Power_W=100mW, Supplier Part Number 1=541-1.18KHCT-ND, TempCo="100 ppm/C", Tolerance_%=1%, Value2=0.1W, Value_Code=1k18, ValueDisplayed=1.18k
R14: library part CMP-0025854-3, "RES, 75, 5%, 0.1 W, 0603", Manufacturer=Vishay-Dale, Power_W=100mW, Supplier Part Number 1=541-75GCT-ND, TempCo="200 ppm/C", Tolerance_%=5%, Value2=0.1W, Value_Code=75R0, ValueDisplayed=75
R15: library part CMP-0078581-1, "RES, 1.00 k, 0.1%, 0.1 W, AEC-Q200 Grade 0, 0603", Manufacturer=Panasonic, Power_W=100mW, Supplier Part Number 1=P1.0KDBCT-ND, TempCo="25 ppm/C", Tolerance_%=0.1%, Value2=0.1W, Value_Code=1k00, ValueDisplayed=1.00k
R16: library part CMP-0022588-5, "RES, 750, 1%, 0.1 W, AEC-Q200 Grade 0, 0603", Manufacturer=Vishay-Dale, Power_W=100mW, Supplier Part Number 1=541-750HCT-ND, TempCo="100 ppm/C", Tolerance_%=1%, Value2=0.1W, Value_Code=750R, ValueDisplayed=750
R17: library part CMP-0024432-2, "RES, 6.19 k, 0.1%, 0.1 W, 0603", Manufacturer="Yageo America", Power_W=100mW, TempCo="25 ppm/C", Tolerance_%=0.1%, Value2=0.1W, Value_Code=6k19, ValueDisplayed=6.19k
R19: library part CMP-0023838-3, "RES, 18.7 k, 0.1%, 0.1 W, 0603", Manufacturer="Yageo America", Power_W=100mW, TempCo="25 ppm/C", Tolerance_%=0.1%, Value2=0.1W, Value_Code=18k7, ValueDisplayed=18.7k
R21 R58 R59: library part CMP-0022759-5, "RES, 118, 1%, 0.1 W, 0603", Manufacturer=Yageo, Power_W=100mW, Supplier Part Number 1=311-118HRCT-ND, TempCo="100 ppm/C", Tolerance_%=1%, Value2=0.1W, Value_Code=118R, ValueDisplayed=118
R22 R38: library part CMP-0022801-5, "RES, 147, 1%, 0.1 W, 0603", Manufacturer=Yageo, Power_W=100mW, Supplier Part Number 1=311-147HRCT-ND, TempCo="100 ppm/C", Tolerance_%=1%, Value2=0.1W, Value_Code=147R, ValueDisplayed=147
R25 R26 R34 R35 R42 R43 R44 R53: library part CMP-0022746-5, "RES, 10.0 k, 1%, 0.1 W, 0603", Manufacturer=Yageo, Power_W=100mW, Supplier Part Number 1=311-10.0KHRCT-ND, TempCo="100 ppm/C", Tolerance_%=1%, Value2=0.1W, Value_Code=10k0, ValueDisplayed=10.0k
R27: library part CMP-0023050-5, "RES, 35.7 k, 1%, 0.1 W, 0603", Manufacturer=Yageo, Power_W=100mW, Supplier Part Number 1=311-35.7KHRCT-ND, TempCo="100 ppm/C", Tolerance_%=1%, Value2=0.1W, Value_Code=35k7, ValueDisplayed=35.7k
R30: library part CMP-0025908-5, "RES, 2.7 k, 5%, 0.1 W, 0603", Manufacturer=Yageo, Power_W=100mW, Supplier Part Number 1=311-2.7KGRCT-ND, TempCo="100 ppm/C", Tolerance_%=5%, Value2=0.1W, Value_Code=2k70, ValueDisplayed=2.7k
R31: library part CMP-0022274-4, "RES, 2.32 k, 1%, 0.1 W, AEC-Q200 Grade 0, 0603", Manufacturer=Vishay-Dale, Power_W=100mW, Supplier Part Number 1=541-2.32KHCT-ND, TempCo="100 ppm/C", Tolerance_%=1%, Value2=0.1W, Value_Code=2k32, ValueDisplayed=2.32k
R32 R45: library part CMP-0022228-4, "RES, 23.2 k, 1%, 0.1 W, AEC-Q200 Grade 0, 0603", Manufacturer=Vishay-Dale, Power_W=100mW, Supplier Part Number 1=541-23.2KHCT-ND, TempCo="100 ppm/C", Tolerance_%=1%, Value2=0.1W, Value_Code=23k2, ValueDisplayed=23.2k
R39: library part CMP-0024668-3, "RES, 13.0 k, 0.5%, 0.1 W, 0603", Manufacturer="Yageo America", Power_W=100mW, TempCo="50 ppm/C", Tolerance_%=0.5%, Value2=0.1W, Value_Code=13k0, ValueDisplayed=13.0k
R40: library part CMP-0024769-3, "RES, 18.2 k, 0.5%, 0.1 W, 0603", Manufacturer="Yageo America", Power_W=100mW, TempCo="50 ppm/C", Tolerance_%=0.5%, Value2=0.1W, Value_Code=18k2, ValueDisplayed=18.2k
R47 R52: library part CMP-0022277-4, "RES, 2.49 k, 1%, 0.1 W, AEC-Q200 Grade 0, 0603", Manufacturer=Vishay-Dale, Power_W=100mW, Supplier Part Number 1=541-2.49KHCT-ND, TempCo="100 ppm/C", Tolerance_%=1%, Value2=0.1W, Value_Code=2k49, ValueDisplayed=2.49k
R49: library part CMP-0022000-4, "RES, 10.5 k, 1%, 0.1 W, AEC-Q200 Grade 0, 0603", Manufacturer=Vishay-Dale, Power_W=100mW, Supplier Part Number 1=541-10.5KHCT-ND, TempCo="100 ppm/C", Tolerance_%=1%, Value2=0.1W, Value_Code=10k5, ValueDisplayed=10.5k
R51: library part CMP-0024637-3, "RES, 12.1 k, 0.5%, 0.1 W, 0603", Manufacturer="Yageo America", Power_W=100mW, TempCo="50 ppm/C", Tolerance_%=0.5%, Value2=0.1W, Value_Code=12k1, ValueDisplayed=12.1k
R54: library part CMP-0023267-5, "RES, 75.0 k, 1%, 0.1 W, 0603", Manufacturer=Yageo, Power_W=100mW, Supplier Part Number 1=311-75.0KHRCT-ND, TempCo="100 ppm/C", Tolerance_%=1%, Value2=0.1W, Value_Code=75k0, ValueDisplayed=75.0k
R55: library part CMP-0022945-5, "RES, 24.0 k, 1%, 0.1 W, 0603", Manufacturer=Yageo, Power_W=100mW, Supplier Part Number 1=311-24.0KHRCT-ND, TempCo="100 ppm/C", Tolerance_%=1%, Value2=0.1W, Value_Code=24k0, ValueDisplayed=24.0k
R56 R57: library part CMP-0025904-5, "RES, 270, 5%, 0.1 W, 0603", Manufacturer=Yageo, Power_W=100mW, Supplier Part Number 1=311-270GRCT-ND, TempCo="100 ppm/C", Tolerance_%=5%, Value2=0.1W, Value_Code=270R, ValueDisplayed=270
S1 S2: library part CMP-0002134-3, "Switch, Tactile, SPST-NO, 0.05A, 12V, SMT", CurrentRating_mA=50A, Manufacturer="TE Connectivity", Supplier Part Number 1=450-1129-ND
TP1 TP3 TP6 TP8 TP9 TP10: library part CMP-1672-00004-3, "Test Point, White, Through Hole, RoHS, Bulk", Colour=White, Package Quantity=100
TP2 TP5 TP7 TP11 TP20 TP21: library part CMP-0003825-1, "1mm Test Point, SMT", Manufacturer=Any
TP4 TP12 TP22 TP23: library part CMP-1672-00002-4, "Test Point, Red, Through Hole, RoHS, Bulk", Colour=Red, Manufacturer=Keystone, Package Quantity=100
TP13 TP14 TP15 TP16 TP17 TP19: library part CMP-1672-00003-4, "Test Point, Black, Through Hole, RoHS, Bulk", Colour=Black, Manufacturer=Keystone, Package Quantity=100
U1: library part CMP-0090278-3, "18V, 1A H-bridge motor driver, PWM, PH/EN, ½ bridge control, with low power sleep mode", Manufacturer="Texas Instruments", Max Supply Voltage=18V, Min Supply Voltage=4.5V, Operating Temperature Range="-40°C to +150°C", Switching Frequency=100kHz
U2: library part CMP-0859-00648-4, "IC FF D-TYPE SNGL 1BIT US8", Ambient Temperature Range High=+125°C, Ambient Temperature Range Low=-40°C, Frequency=140MHz, Manufacturer="Texas Instruments", Max Supply Voltage=5.5V, Min Supply Voltage=1.65V, Nominal Supply Current=10uA, Package=DCU0008A, Temperature="-40°C to +125°C"
U3: library part CMP-0750213-2, "INA293 High-Voltage, High Bandwidth, Unidirectional, 110-V Common-Mode, Current-Sense Amplifier, DBV0005A (SOT-23-5)", Alternate Manufacturer="Texas Instruments", Alternate PartNumber=INA293A1IDBVT
U4: library part CMP-0860894-1, "Low power, small size comparator with push-pull output, DCK0005A (SOT-SC70-5)", Alternate Manufacturer="Texas Instruments", Alternate PartNumber=TLV7011DCKT, Operating Temperature Range="-40 to 125 C", Rating=Catalog
U5: library part CMP-0127189-1, "Dual, 5.5V, 20MHz, zero-cross low-noise (6nV/√Hz) RRIO operational amplifier 8-VSSOP -40 to 125", Digikey Part Number=296-OPA2323IDGKRCT-ND, Input Bias Current=0.5pA, Input Offset Voltage=0.15mV, Manufacturer="Texas Instruments", Max Dual Supply Voltage=2.75V, Max Supply Voltage=5.5V, Min Dual Supply Voltage=850mV, Min Supply Voltage=1.7V, Mouser Part Number=595-OPA2323IDGKR, Nominal Supply Current=1.6mA, Operating Temperature Range="-40°C to +125°C", Output Current Per Channel=110mA, Voltage Gain=120dB
U6: library part CMP-0128101-1, "40V, wide common-mode voltage (-40V to 85V) difference amplifier with fixed attenuation ratios 6-SOT-23 -40 to 125", Digikey Part Number=296-INA600AIDBVRCT-ND, Manufacturer="Texas Instruments", Max Dual Supply Voltage=20V, Max Supply Voltage=40V, Min Dual Supply Voltage=1.35V, Min Supply Voltage=2.7V, Mouser Part Number=595-INA600AIDBVR, Operating Temperature Range="-40°C to +125°C", Output Current Per Channel=50mA
U7: library part CMP-0128112-1, "Quad, zero-drift, micropower (65μA), high speed-to-power ratio (2.5MHz) RRIO operational amplifier 14-TSSOP -40 to 125", Digikey Part Number=296-OPA4383PWRCT-ND, Input Bias Current=10pA, Input Offset Voltage=0.4uV, Manufacturer="Texas Instruments", Max Dual Supply Voltage=2.75V, Max Supply Voltage=5.5V, Min Dual Supply Voltage=850mV, Min Supply Voltage=1.7V, Operating Temperature Range="-40°C to +125°C", Output Current Per Channel=28mA, Voltage Gain=145dB
U8 U10: library part CMP-0122167-3, "Precision, Self-Latching Comparator", Input Bias Current=0.000005uA, Input Offset Voltage=0.3mV, Manufacturer="Texas Instruments", Max Supply Voltage=5.5V, Min Supply Voltage=1.65V, Nominal Supply Current=20uA, Operating Temperature Range="-40°C to +125°C", Output Current Per Channel=100mA
U9: library part CMP-0051579-2, "Single 2-Input Positive-AND Gate, DBV0005A (SOT-23-5)", F @ Nom Voltage(Max)(Mhz)=75, Generic Part Number=SN74AHCT1G08, ICC @ Nom Voltage(Max)(mA)=0.01, Manufacturer="Texas Instruments", Operating Temperature Range="-40 to 125 C", Rating=Catalog, tpd @ Nom Voltage(Max)(ns)=7.1, Voltage(Nom)(V)=5
U11: library part CMP-0079546-2, "1-A, Positive Voltage Regulator, DRV0006A (WSON-6)", Alternate Manufacturer="Texas Instruments"
U12: library part CMP-0033015-1, "Low-Voltage Adjustable Precision Shunt Regulator, 15 mA, -40 to 125 degC, 3-pin SOT-23 (DBZ), Green (RoHS & no Sb/Br)", Manufacturer="Texas Instruments", Rating=Catalog, Temp Coeff(Max)(ppm/ degree C)=129
ZZ1: library part CMP-0077236-1
ZZ2: library part CMP-0077237-1
ZZ3: library part CMP-0077238-1
ZZ4: library part CMP-0003616-3

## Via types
v1: diameter 34, hole 16, Top Layer to Bottom Layer, tented both sides, 184 vias
v2: diameter 19.68, hole 7.87, Top Layer to Bottom Layer, 2 vias

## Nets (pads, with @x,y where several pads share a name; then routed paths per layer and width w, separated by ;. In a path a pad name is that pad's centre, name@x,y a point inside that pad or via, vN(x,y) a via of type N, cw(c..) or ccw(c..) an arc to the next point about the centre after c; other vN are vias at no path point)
3V3: C3.1 C4.1 C5.1 C7.1 C8.1 C10.1 C14.1 C17.1 C18.1 D1.2 J8.2 R4.2 R10.1 R14.1 R25.1 R26.1 R34.1 R42.1 R43.1 R44.1 R58.2 R59.2 TP23.1 U2.7 U2.8 U3.5 U4.5 U5.8 U6.6 U7.4 U8.6 U9.5 U10.6 | length 1878.7
  Top Layer w10: R59.2@260.08,1626.51 266.59,1620 v1(310,1620) ; v1(360,1620) 408.5,1620 R58.2@410,1621.5 ; R10.1@492.76,2337.72 v1(492.76,2377.09) ; v1(520,1610) 568.5,1610 R42.1@570,1611.5 ; C5.1@542.13,2170.24 550,2162.36 v1(550,2130) ; C5.1@550,2170.24 550.98,2170.24 564.69,2183.94 564.69,2185.82 568.66,2189.79 568.66,2248.2 569.44,2248.98 U2.7@571.65,2248.98 ; R34.1@560,1281.5 v1(560,1340) ; v1(840,330) 895.37,330 D1.2@900.47,324.9 ; R4.2@840,2098.5 R4.2@840,2100 ; R4.2@849.02,2088.5 859.56,2077.96 860,2077.96 886.35,2051.61 908.39,2051.61 v1(910,2050) 971.1,2050 C4.1@973.23,2052.13 ; v1(860,2290) 898.5,2290 C3.1@900,2288.5 ; U4.5@960.43,2124.96 960.43,2065.83 964.29,2061.97 C4.1@965.35,2061.97 ; v1(975.2,2012.76) C4.1@975.2,2052.13 ; v1(1035.47,664.67) 1035.71,664.9 C14.1@1070.47,664.9 ; 1100,668.5 1189.57,668.5 1190.47,667.6 U8.6@1190.47,664.9 ; C18.1@1151.5,230 1157.4,235.91 1157.4,254.61 U9.5@1157.4,285.87 ; C18.1@1170.87,230 v1(1210,230) ; v1(1200,2010) 1205.55,2010 1230.47,1985.08 C10.1@1230.47,1974.9 ; C10.1@1240.16,1974.41 1240.16,1975.39 1253.86,1989.09 1370.91,1989.09 1387.16,1972.84 1387.16,1935.67 U7.4@1387.8,1935.04 ; U5.8@1263.39,951.61 1263.39,885.12 C7.1@1268.5,880 ; C7.1@1265.1,870.47 1265.1,835.71 v1(1265.33,835.47) ; R26.1@1319.53,515.1 1354.29,515.1 v1(1354.53,515.33) ; R25.1@1339.53,455.1 1374.29,455.1 v1(1374.53,455.33) ; R43.1@1365.1,290.47 1365.1,255.71 v1(1365.33,255.47) ; v1(1395.47,614.67) 1395.71,614.9 C17.1@1430.47,614.9 ; C17.1@1440,618.5 1529.57,618.5 1530.47,617.6 U10.6@1530.47,614.9 ; R14.1@1620,928.5 1668.5,928.5 v1(1670,930) ; R44.1@1666.18,540.32 1691.27,565.41 1705.41,565.41 v1(1710,570)
  Top Layer w19.68: v1(1240,2500) 1241.5,2501.5 C8.1@1320,2501.5 ; C8.1@1320.09,2500 1346.06,2501.5 1357.17,2512.6 U6.6@1378.82,2512.6
  Top Layer w25: C3.1@900,2288.5 900,2287.52 906.2,2281.32 907.19,2281.32 908.5,2280 U3.5@970,2280
  other v1: 212.49,1680.47 256.87,1680.47 301.24,1680.47 345.62,1680.47 390,1680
